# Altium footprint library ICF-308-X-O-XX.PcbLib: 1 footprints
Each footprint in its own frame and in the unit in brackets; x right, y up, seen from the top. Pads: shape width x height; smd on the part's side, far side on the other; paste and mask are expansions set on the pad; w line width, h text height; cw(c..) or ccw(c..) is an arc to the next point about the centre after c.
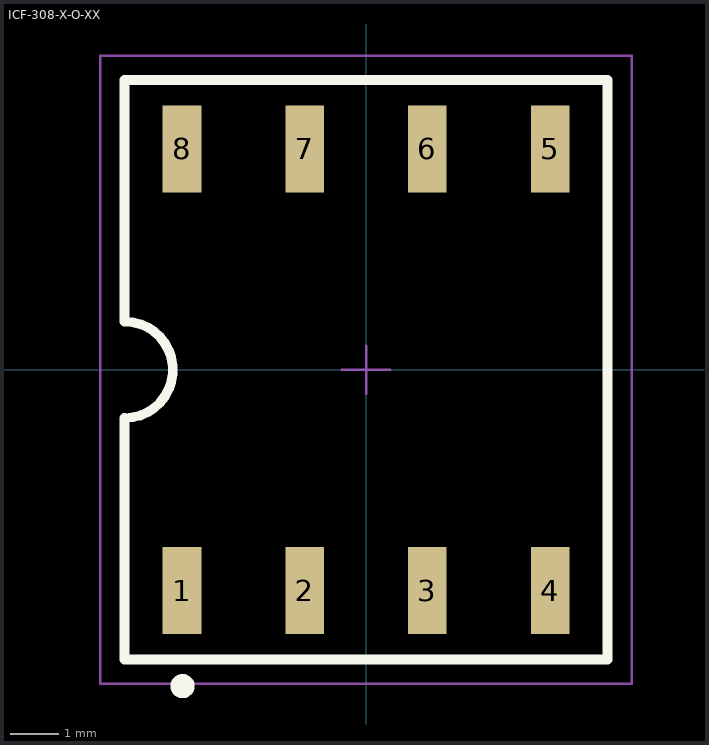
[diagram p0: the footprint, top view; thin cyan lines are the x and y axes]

## ICF-308-X-O-XX [mm] "2.54mm pitch, 8 pin, dip socket; 7.62mm LS"
height 4.57
pads (8):
  rect 0.8x1.8 smd mask+0: 1(-3.81,-4.572) 2(-1.27,-4.572) 3(1.27,-4.572) 4(3.81,-4.572) 5(3.81,4.572) 6(1.27,4.572) 7(-1.27,4.572) 8(-3.81,4.572)
Top Overlay:
  circle w0.25: c-3.8,-6.55 r0.125
  lines w0.2: -5,-6 -5,-1 ccw(c-5,0) -5,1 -5,6 5,6 5,-6 -5,-6
Mechanical 12:
  lines w0.001: -5,-1 -5,-6 5,-6 5,6 -5,6 -5,1
Mechanical 13:
  lines w0.1: -5,-6 -5,-1 ccw(c-5,0) -5,1 -5,6 5,6 5,-6 -5,-6
  text ".Designator" at 0.254,0.254 h1.52
Mechanical 15:
  lines w0.05: -0.5,0 0.5,0 ; 0,-0.5 0,0.5 ; -5.5,-6.5 5.5,-6.5 5.5,6.5 -5.5,6.5 -5.5,-6.5
Mechanical 16:
  lines w0.001: -5,-1 ccw(c-5,0) -5,1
